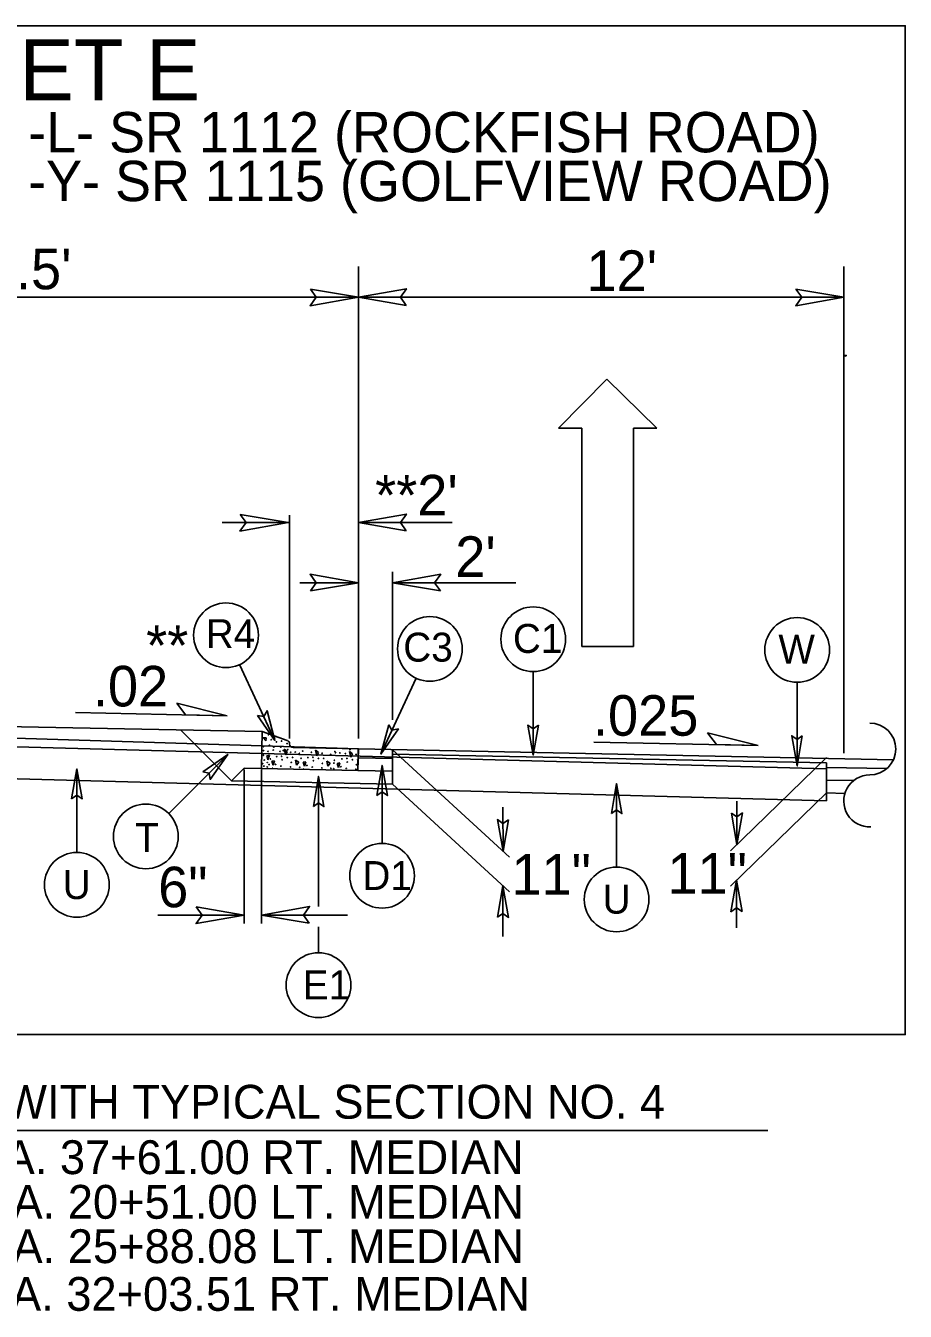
# Model space of a CAD drawing. Extents: x 958711 to 962106, y 831169 to 840840.
# Drawn here: x 959956.9 to 960126.2, y 838795 to 839042.5 of the extents above; entities that cross this region are included whole.
import ezdxf

# ---------------------------------------------------------------- set-up
doc = ezdxf.new("R2010")
doc.units = 0
for name, color, linetype in [('Default', 7, 'Continuous'), ('Old_Level_1', 7, 'Continuous'), ('Old_Level_11', 7, 'Continuous'), ('Old_Level_3', 7, 'Continuous'), ('Prop Dimension Text', 7, 'Continuous'), ('Prop Lane Arrow CELL', 7, 'Continuous'), ('Typical Curb CELL', 7, 'Continuous'), ('Typical ID Circle CELL', 7, 'Continuous'), ('Typical Terminator CELL', 7, 'Continuous'), ('Typical Text ID Circle CELL', 7, 'Continuous')]:
    doc.layers.add(name, color=color, linetype=linetype)

# ---------------------------------------------------------------- blocks, each defined once
blk = doc.blocks.new('Lane Arrow Through')
at = {"layer": 'Prop Lane Arrow CELL'}
for p, q in [((-3.15, 1.6), (-3.15, 3.1)), ((-3.15, 3.1), (0, 0)), ((-17.15, 1.6), (-3.15, 1.6)), ((-17.15, -1.7), (-17.15, 1.6)), ((0, 0), (-3.15, -3.2)), ((-3.15, -1.7), (-17.15, -1.7)), ((-3.15, -3.2), (-3.15, -1.7))]:
    blk.add_line(p, q, dxfattribs=at)

msp = doc.modelspace()

# ---------------------------------------------------------------- linework, layer by layer
at = {"layer": 'Default'}
for p, q in [((959952.78, 838907.6), (960002.43, 838906.61)), ((959996.52, 838897.1), (959986.7, 838906.92))]:
    msp.add_line(p, q, dxfattribs=at)
at = {"layer": 'Old_Level_1'}
for p, q in [((960020.95, 838996.13), (960020.95, 838905.27)), ((960114.43, 838996.13), (960114.43, 838902.42)), ((959884.62, 838990.21), (960020.95, 838990.21)), ((960020.95, 838990.21), (960114.43, 838990.21)), ((960114.43, 838978.96), (960114.86, 838978.96)), ((960007.72, 838948.27), (960007.72, 838905.27)), ((959994.73, 838946.83), (960007.72, 838946.83)), ((960020.95, 838946.83), (960039.02, 838946.83)), ((960027.55, 838908.86), (960027.55, 838937.33)), ((960020.95, 838935.26), (960009.68, 838935.26)), ((960027.55, 838935.26), (960051.28, 838935.26)), ((959966.5, 838910.25), (959995.71, 838909.66)), ((959952.78, 838905.4), (960020.95, 838903.26)), ((960066.3, 838904.57), (960097.9, 838903.94)), ((960020.91, 838901.53), (960027.55, 838901.4)), ((960020.95, 838903.26), (960123.95, 838901.17)), ((960027.55, 838903.12), (960050.06, 838882.41)), ((960027.55, 838896.47), (960027.55, 838903.12)), ((960027.55, 838902.26), (960111.06, 838900.57)), ((960111.09, 838901.61), (960092.61, 838883.68)), ((959998.98, 838899.56), (959996.52, 838897.1)), ((959998.98, 838899.56), (960002.28, 838899.5)), ((959998.98, 838869.66), (959998.98, 838899.31)), ((960002.28, 838869.66), (960002.28, 838899.31)), ((960020.86, 838899.1), (960027.55, 838898.97)), ((960111.06, 838899.45), (960111.06, 838900.57)), ((960111.06, 838899.71), (960122.68, 838899.47)), ((960111.06, 838899.45), (960111.06, 838893.27)), ((959996.52, 838897.1), (960027.55, 838896.47)), ((960027.55, 838896.47), (960050.06, 838875.76)), ((960111.06, 838897.28), (960116.31, 838897.17)), ((960111.06, 838894.79), (960092.59, 838876.86)), ((960111.06, 838894.79), (960114.62, 838894.71)), ((960048.79, 838892.08), (960048.8, 838883.57)), ((960093.83, 838893.22), (960093.83, 838884.86)), ((960048.78, 838876.93), (960048.78, 838867.16)), ((960093.76, 838878.03), (960093.76, 838868.81)), ((959982.38, 838871.3), (959998.98, 838871.3)), ((960002.28, 838871.3), (960018.88, 838871.3)), ((959810.36, 838829.82), (960099.79, 838829.82))]:
    msp.add_line(p, q, dxfattribs=at)
msp.add_lwpolyline([(959767.63, 839042.47), (960126.24, 839042.47), (960126.24, 838848.28), (959767.63, 838848.28)], close=True, dxfattribs=at)
for points in [[(959952.78, 838903.76), (960111.06, 838899.45)], [(959952.94, 838897.58), (960111.06, 838893.27)]]:
    msp.add_lwpolyline(points, dxfattribs=at)
for centre, start, end in [((960119.4, 838903.25), 270, 90), ((960119.4, 838893.25), 90, 272.2728)]:
    msp.add_arc(centre, 5, start, end, dxfattribs=at)
at = {"layer": 'Old_Level_11'}
for p, q in [((959987.71, 838909.82), (959985.98, 838912.08)), ((959985.98, 838912.08), (959995.71, 838909.66)), ((959995.71, 838909.66), (959987.71, 838909.82)), ((960089.9, 838904.1), (960088.17, 838906.35)), ((960088.17, 838906.35), (960097.9, 838903.94)), ((960097.9, 838903.94), (960089.9, 838904.1))]:
    msp.add_line(p, q, dxfattribs=at)
at = {"layer": 'Typical Curb CELL'}
for p, q in [((960002.28, 838899.5), (960002.43, 838906.61)), ((960007.28, 838904.88), (960002.43, 838906.61)), ((960003.22, 838905.41), (960002.6, 838905.42)), ((960002.6, 838905.42), (960003.17, 838904.8)), ((960003.17, 838904.8), (960003.22, 838905.41)), ((960007.72, 838904.2), (960007.72, 838904.24)), ((960020.95, 838903.26), (960008.38, 838903.52)), ((960003.83, 838902.04), (960003.31, 838901.95)), ((960003.31, 838901.95), (960003.55, 838901.17)), ((960003.55, 838901.17), (960003.83, 838902.04)), ((960004.82, 838900.99), (960004.31, 838900.9)), ((960004.31, 838900.9), (960004.55, 838900.12)), ((960004.55, 838900.12), (960004.82, 838900.99)), ((960006.7, 838903.2), (960006.97, 838902.13)), ((960007.28, 838902.77), (960006.7, 838903.2)), ((960006.97, 838902.13), (960007.28, 838902.77)), ((960008.85, 838901.1), (960009.48, 838900.73)), ((960009.05, 838900.16), (960008.85, 838901.1)), ((960012.72, 838903.02), (960012.99, 838901.95)), ((960013.29, 838902.59), (960012.72, 838903.02)), ((960012.99, 838901.95), (960013.29, 838902.59)), ((960014.86, 838900.91), (960015.5, 838900.55)), ((960015.07, 838899.98), (960014.86, 838900.91)), ((960019.26, 838902.77), (960019.53, 838901.7)), ((960019.83, 838902.34), (960019.26, 838902.77)), ((960019.53, 838901.7), (960019.83, 838902.34)), ((960020.95, 838903.26), (960020.86, 838899.1)), ((960020.86, 838899.1), (960020.94, 838903.21)), ((960020.86, 838899.1), (960002.28, 838899.5)), ((960009.48, 838900.73), (960009.05, 838900.16)), ((960010.84, 838900.81), (960010.32, 838900.72)), ((960010.32, 838900.72), (960010.57, 838899.94)), ((960010.57, 838899.94), (960010.84, 838900.81)), ((960015.5, 838900.55), (960015.07, 838899.98)), ((960017.38, 838900.56), (960016.86, 838900.47)), ((960016.86, 838900.47), (960017.11, 838899.69)), ((960017.11, 838899.69), (960017.38, 838900.56))]:
    msp.add_line(p, q, dxfattribs=at)
for centre in [(960003.68, 838906.01), (960002.67, 838903.71), (960003.83, 838903.98), (960004.18, 838905.04), (960004.66, 838903.61), (960004.82, 838905.4), (960005.19, 838904.63), (960006.01, 838903.61), (960006.16, 838904.77), (960007.24, 838904.31), (960002.68, 838902.05), (960002.71, 838902.94), (960002.83, 838901.13), (960003.59, 838902.8), (960004.04, 838901.33), (960004.57, 838903.05), (960005.23, 838901.78), (960005.89, 838902.8), (960006.19, 838901.86), (960006.28, 838901.18), (960006.48, 838902.96), (960007.25, 838901.61), (960007.35, 838903.13), (960007.95, 838902.63), (960008.28, 838901.62), (960008.79, 838902.67), (960009.62, 838902.4), (960009.93, 838901.46), (960010.25, 838902.85), (960011.24, 838901.6), (960011.91, 838902.62), (960012.21, 838901.68), (960012.29, 838901), (960013.27, 838901.43), (960013.96, 838902.44), (960014.3, 838901.44), (960015.63, 838902.22), (960016.36, 838901.09), (960016.45, 838902.75), (960016.56, 838902.54), (960017.39, 838902.49), (960017.78, 838901.35), (960018.45, 838902.37), (960018.75, 838901.43), (960019.33, 838903.15), (960019.81, 838901.18), (960020.51, 838902.2), (960020.84, 838901.19), (960002.53, 838900.45), (960002.79, 838899.96), (960003.4, 838899.8), (960003.77, 838900.26), (960005.03, 838900.28), (960006.06, 838899.96), (960007.92, 838899.8), (960008.04, 838900.66), (960009.66, 838899.73), (960011.05, 838900.09), (960012.07, 838899.78), (960013.94, 838899.61), (960014.05, 838900.48), (960015.67, 838899.55), (960016.22, 838899.44), (960016.24, 838900.53), (960017.59, 838899.84), (960018.61, 838899.53), (960018.83, 838900.75), (960020.48, 838899.37), (960020.59, 838900.23)]:
    msp.add_circle(centre, 0.0452, dxfattribs=at)
for centre, radius, start, end in [((960007.06, 838904.25), 0.667, 358.794, 70.359), ((960008.39, 838904.19), 0.667, 178.794, 268.794), ((960003.41, 838900.6), 0.0452, 25.8325, 153.0355), ((960004.41, 838899.55), 0.0452, 25.8325, 153.0355), ((960010.43, 838899.37), 0.0452, 25.8325, 153.0355)]:
    msp.add_arc(centre, radius, start, end, dxfattribs=at)
at = {"layer": 'Typical ID Circle CELL'}
for p, q in [((959998.1, 838919.5), (960004.9, 838904.92)), ((960032.1, 838916.87), (960025.29, 838902.29)), ((960054.62, 838918.15), (960054.62, 838902.07)), ((960105.43, 838916.1), (960105.43, 838900.01)), ((959984.44, 838890.84), (959995.82, 838902.21)), ((959966.76, 838883.34), (959966.76, 838899.42)), ((960025.52, 838885.08), (960025.52, 838900.09)), ((960013.28, 838872.94), (960013.28, 838897.97)), ((960070.67, 838880.53), (960070.67, 838896.61)), ((960013.28, 838864.03), (960013.28, 838869.01))]:
    msp.add_line(p, q, dxfattribs=at)
for centre in [(959995.47, 838925.14), (960054.62, 838924.38), (960034.72, 838922.51), (960105.43, 838922.32), (959980.04, 838886.43), (960025.52, 838878.85), (959966.76, 838877.11), (960070.67, 838874.3), (960013.28, 838857.8)]:
    msp.add_circle(centre, 6.23, dxfattribs=at)
at = {"layer": 'Typical Terminator CELL'}
msp.add_line((960114.86, 838978.89), (960114.86, 838979.04), dxfattribs=at)
for points in [[(960011.72, 838991.79), (960020.95, 838990.21), (960011.67, 838988.57), (960012.85, 838990.21)], [(960030.17, 838988.62), (960020.95, 838990.21), (960030.22, 838991.85), (960029.04, 838990.21)], [(960105.2, 838991.79), (960114.43, 838990.21), (960105.15, 838988.57), (960106.33, 838990.21)], [(959998.2, 838948.41), (960007.43, 838946.83), (959998.15, 838945.19), (959999.33, 838946.83)], [(960030.17, 838945.24), (960020.95, 838946.83), (960030.22, 838948.47), (960029.04, 838946.83)], [(960011.72, 838933.67), (960020.95, 838935.26), (960011.67, 838936.9), (960012.85, 838935.26)], [(960036.77, 838933.67), (960027.55, 838935.26), (960036.82, 838936.9), (960035.64, 838935.26)], [(960001.56, 838909.73), (960004.9, 838904.92), (960003.38, 838910.61), (960002.76, 838909.51)], [(960026.83, 838907.93), (960025.29, 838902.29), (960028.67, 838907.11), (960027.43, 838906.88)], [(960055.62, 838907.83), (960054.62, 838902.07), (960053.6, 838907.86), (960054.62, 838907.13)], [(960106.42, 838905.77), (960105.43, 838900.01), (960104.4, 838905.8), (960105.43, 838905.07)], [(959991.04, 838898.84), (959995.82, 838902.21), (959992.45, 838897.39), (959992.24, 838898.63)], [(959965.76, 838893.66), (959966.76, 838899.42), (959967.78, 838893.63), (959966.76, 838894.37)], [(960024.53, 838894.33), (960025.52, 838900.09), (960026.54, 838894.3), (960025.52, 838895.03)], [(960012.29, 838892.2), (960013.28, 838897.97), (960014.31, 838892.17), (960013.28, 838892.91)], [(960069.68, 838890.85), (960070.67, 838896.61), (960071.69, 838890.82), (960070.67, 838891.55)], [(960049.84, 838889.64), (960048.8, 838883.57), (960047.72, 838889.67), (960048.79, 838888.9)], [(960092.78, 838890.92), (960093.83, 838884.86), (960094.9, 838890.96), (960093.83, 838890.18)], [(960047.74, 838870.87), (960048.78, 838876.93), (960049.86, 838870.83), (960048.78, 838871.61)], [(960094.81, 838871.97), (960093.76, 838878.03), (960092.68, 838871.93), (960093.76, 838872.71)], [(959989.76, 838872.88), (959998.98, 838871.3), (959989.71, 838869.66), (959990.89, 838871.3)], [(960011.51, 838869.71), (960002.28, 838871.3), (960011.56, 838872.94), (960010.38, 838871.3)]]:
    msp.add_lwpolyline(points, close=True, dxfattribs=at)
msp.add_lwpolyline([(960114.86, 838979.04), (960114.43, 838978.96), (960114.86, 838978.89)], dxfattribs=at)

# ---------------------------------------------------------------- block references
at = {"layer": 'Old_Level_1', "xscale": 3, "yscale": 3, "rotation": 90}
msp.add_blockref('Lane Arrow Through', (960068.79, 838974.46), dxfattribs=at)

# ---------------------------------------------------------------- texts
at = {"layer": 'Old_Level_1'}
for s, height, p in [('INSET E', 11.716, (959929.59, 839028.13)), ('USE INSET E FOR R4 (2\'-9" C & G) WITH TYPICAL SECTION NO. 4', 6.5088, (959810.22, 838832.1))]:
    msp.add_text(s, height=height, dxfattribs=at).set_placement(p)
at = {"layer": 'Old_Level_11'}
msp.add_text('11"', height=7.801, dxfattribs=at).set_placement((960080.45, 838875.41))
at = {"layer": 'Old_Level_3'}
for s, p in [('**-L- STA. 31+47.24 TO STA. 37+61.00 RT. MEDIAN', (959846.68, 838821.43)), ('*-Y- STA. 19+66.71 TO STA. 20+51.00 LT. MEDIAN', (959850.62, 838812.84)), ('*-Y- STA. 23+40.00 TO STA. 25+88.08 LT. MEDIAN', (959850.62, 838804.3)), ('**-Y- STA. 25+88.08 TO STA. 32+03.51 RT. MEDIAN', (959846.95, 838795.12))]:
    msp.add_text(s, height=6.5088, dxfattribs=at).set_placement(p)
at = {"layer": 'Prop Dimension Text'}
for s, height, rotation, p in [('-L- SR 1112 (ROCKFISH ROAD)', 7.7675, 0, (959957.38, 839018.09)), ('-Y- SR 1115 (GOLFVIEW ROAD)', 7.7675, 0, (959957.38, 839008.7)), ("17.5'", 7.801, 0, (959943.44, 838991.74)), ("12'", 7.801, 0, (960064.87, 838991.42)), ("**2'", 7.801, 0, (960024.18, 838948.21)), ("2'", 7.801, 0, (960039.61, 838936.39)), ('**', 7.801, 0, (959980.1, 838919.28)), ('.02', 7.801, 360, (959969.85, 838911.45)), ('.025', 7.801, 360, (960066.11, 838905.81)), ('11"', 7.801, 0, (960050.42, 838875.22)), ('6"', 7.801, 0, (959982.42, 838872.79))]:
    msp.add_text(s, height=height, rotation=rotation, dxfattribs=at).set_placement(p)
at = {"layer": 'Typical Text ID Circle CELL'}
for s, height, p in [('R4', 5.572, (959991.58, 838922.67)), ('C3', 5.572, (960029.6, 838920.07)), ('C1', 5.572, (960050.71, 838921.75)), ('W', 5.57, (960101.81, 838919.69)), ('T', 5.57, (959977.98, 838883.42)), ('D1', 5.572, (960021.73, 838876.11)), ('U', 5.57, (959964.05, 838874.37)), ('U', 5.57, (960067.97, 838871.56)), ('E1', 5.572, (960010.25, 838855.06))]:
    msp.add_text(s, height=height, dxfattribs=at).set_placement(p)

doc.saveas('drawing.dxf')
